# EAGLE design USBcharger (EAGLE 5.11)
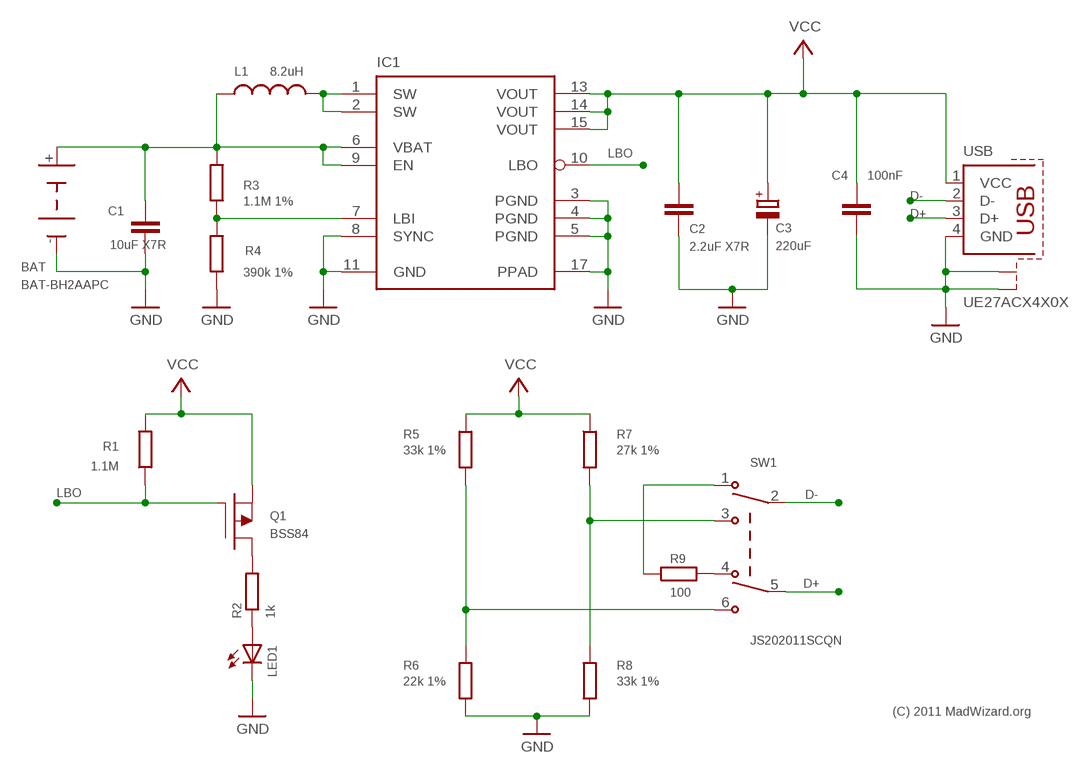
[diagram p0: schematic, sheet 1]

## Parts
BAT  BAT-BH2AAPC  [BH2AAPC]
C1  10uF X7R  C0805  [CAPC2012X130N]
C2  2.2uF X7R  C0805  [CAPC2012X130N]
C3  220uF  CPMLD-B  [CAPMP3528X210N]
C4  100nF  C0603  [CAPC1608X55N]
IC1  TPS61032  [MO-153+PAD]
L1  8.2uH  LWE-HCI-13MM  [7443550820]
LED1  LED0603  [LEDC1608X60N]
Q1  BSS84  PFET_SOT23  [SOT95P240X110-3N]
R1  1.1M  R0603  [RESC1508X63N]
R2  1k  R0603  [RESC1508X63N]
R3  1.1M 1%  R0603  [RESC1508X63N]
R4  390k 1%  R0603  [RESC1508X63N]
R5  33k 1%  R0603  [RESC1508X63N]
R6  22k 1%  R0603  [RESC1508X63N]
R7  27k 1%  R0603  [RESC1508X63N]
R8  33k 1%  R0603  [RESC1508X63N]
R9  100  R0603  [RESC1508X63N]
SW1  JS202011SCQN  [JS202011SCQN]
USB  UE27ACX4X0X  USB-A-RECEPTACLE  [USB-A-RECEPTACLE]

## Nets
D+: SW1.5(2COM) USB.3(D+)
D-: SW1.2(1COM) USB.2(D-)
GND: BAT.- C1.2 C2.2 C3.2(-) C4.2 IC1.3(PGND) IC1.4(PGND) IC1.5(PGND) IC1.8(SYNC) IC1.11(GND) IC1.17(PPAD) LED1.1(C) R4.1 R6.2 R8.2 USB.4(GND) USB.S1 USB.S2
IDEV-: R7.2 R8.1 SW1.3(1B)
LBI: IC1.7(LBI) R3.1 R4.2
LBO: IC1.10(LBO) Q1.1(GATE) R1.1
N$1: Q1.3(DRAIN) R2.2
N$2: R9.1 SW1.1(1A)
N$3: LED1.2(A) R2.1
N$4: R9.2 SW1.4(2A)
RR3: R5.2 R6.1 SW1.6(2B)
SW: IC1.1(SW) IC1.2(SW) L1.2
VBAT: BAT.+ C1.1 IC1.6(VBAT) IC1.9(EN) L1.1 R3.2
VCC: C2.1 C3.1(+) C4.1 IC1.13(VOUT) IC1.14(VOUT) IC1.15(VOUT) Q1.2(SOURCE) R1.2 R5.1 R7.1 USB.1(VCC)

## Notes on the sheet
- (C) 2011 MadWizard.org

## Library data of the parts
BAT = mw-special:BAT-BH2AAPC
C1 C2 C4 = mw-passive:C
C3 = mw-passive:CP
IC1 = mw-ti:TPS61032
L1 = mw-wurth:L
LED1 = mw-diodes:LED
Q1 = mw-transistors:PFET_
R1-R9 = mw-passive:R
SW1 = mw-ck:JS202011SCQN
USB = mw-special:USB-A-RECEPTACLE; OC_FARNELL: unknown; OC_NEWARK: unknown

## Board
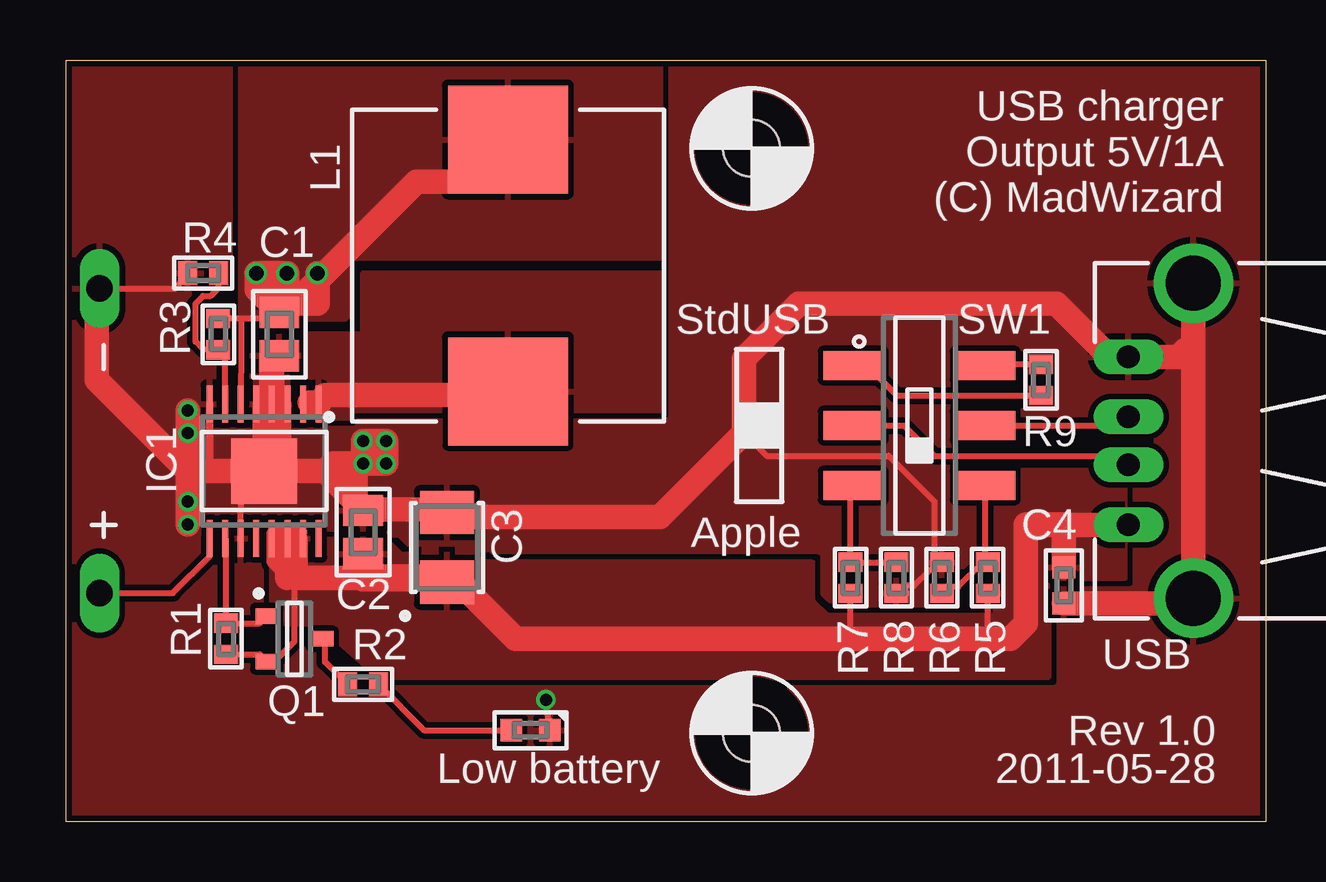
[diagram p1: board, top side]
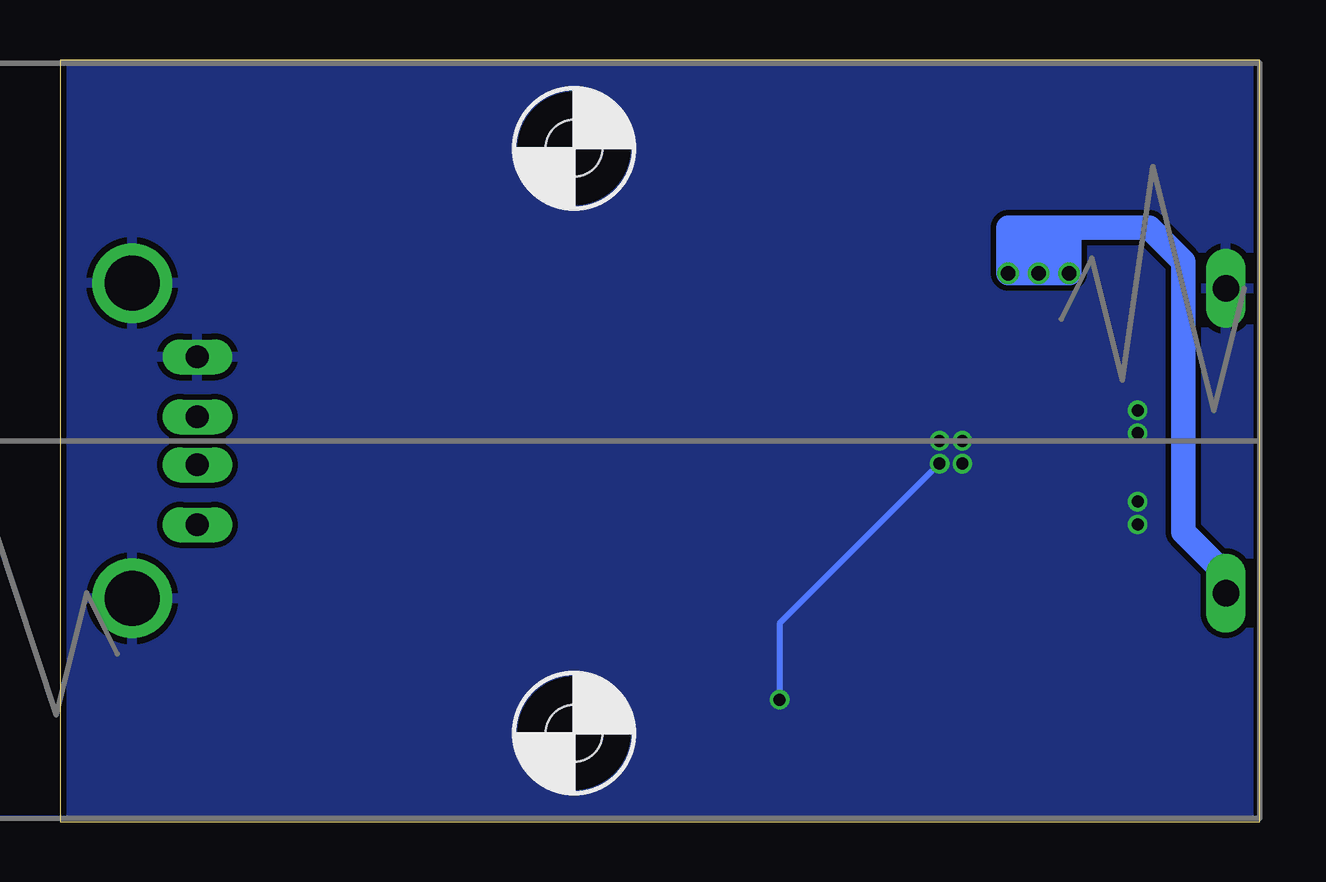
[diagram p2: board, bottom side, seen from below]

Size 50 x 31.75 mm. Coordinates in mm from the lower left corner, seen from the top.
Outline: 0,0 0,31.75 50,31.75 50,0 0,0
Copper layers (1*16): Top 0.035mm / dielectric 1.5mm / Bottom 0.035mm
Design rules "ITead_rule *": minimum track width 8mil, minimum drill 12mil, track to track 9mil, track to pad 9mil, pad to pad 9mil, via to via 9mil, smd to smd 0mil, copper to edge 10mil, drill to drill 10mil, minimum pad ring 10mil, minimum via ring 6mil, stop-mask expansion 2mil, vias tented up to drill 100mil, thermal gap 10mil

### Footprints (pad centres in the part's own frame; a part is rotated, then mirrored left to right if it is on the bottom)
BH2AAPC = drill 1.1 long: + 27.178,-6.35; - 27.178,6.35 | hole 2.362: 0,12.192; 0,-12.192
CAPC2012X130N = smd 1.3 x 1.65: 1 -0.9,0; 2 0.9,0
CAPMP3528X210N = smd 1.8 x 2.25: 1 -1.45,0; 2 1.45,0
CAPC1608X55N = smd 0.9 x 0.95: 1 -0.75,0; 2 0.75,0
MO-153+PAD = smd 0.25 x 1.55: 1 -2.275,-2.8; 2 -1.625,-2.8; 3 -0.975,-2.8; 4 -0.325,-2.8; 5 0.325,-2.8; 6 0.975,-2.8; 7 1.625,-2.8; 8 2.275,-2.8; 9 2.275,2.8; 10 1.625,2.8; 11 0.975,2.8; 12 0.325,2.8; 13 -0.325,2.8; 14 -0.975,2.8; 15 -1.625,2.8; 16 -2.275,2.8 | smd 2.74 x 2.74: 17 0,0
7443550820 = smd 4.5 x 5: 1 -5.25,0; 2 5.25,0
LEDC1608X60N = smd 0.9 x 0.95: 1 -0.8,0; 2 0.8,0
SOT95P240X110-3N = smd 0.95 x 0.65: 1 -1.15,0.95; 2 -1.15,-0.95; 3 1.15,0
RESC1508X63N = smd 0.8 x 1: 1 -0.65,0; 2 0.65,0
JS202011SCQN = smd 1.2 x 2.5: 1 -2.5,-2.75; 2 0,-2.75; 3 2.5,-2.75; 4 -2.5,2.75; 5 0,2.75; 6 2.5,2.75
USB-A-RECEPTACLE = drill 0.95 long: 1 -3.5,2.71; 2 -1,2.71; 3 1,2.71; 4 3.5,2.71 | drill 2.3 pad 2.9 round: S1 -6.57,0; S2 6.57,0

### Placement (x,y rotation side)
BAT  28.57,15.88 0 bottom
C1  8.89,20.32 270 top
C2  12.38,12.06 90 top
C3  15.88,11.43 90 top
C4  41.59,9.84 270 top
IC1  8.26,14.61 180 top
L1  18.41,23.18 270 top
LED1  19.37,3.81 180 top
Q1  9.53,7.62 0 top
R1  6.67,7.62 270 top
R2  12.38,5.71 180 top
R3  6.35,20.32 90 top
R4  5.71,22.86 0 top
R5  38.42,10.16 90 top
R6  36.51,10.16 90 top
R7  32.7,10.16 90 top
R8  34.61,10.16 270 top
R9  40.64,18.41 90 top
SW1  35.56,16.51 270 top
USB  46.99,15.88 90 top

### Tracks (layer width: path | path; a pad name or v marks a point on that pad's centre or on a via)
D+
  Top 0.203: 44.65,16.51 45.09,16.51
  Top 0.254: SW1.5 44.65,16.51 USB.3
D-
  Top 0.203: 43.18,15.24 43.55,14.88
  Top 0.254: SW1.2 34.92,16.51 36.2,15.24 43.18,15.24 | 43.55,14.88 USB.2
GND  (via drill 0.5)
  Top 0.203: 8.58,19.32 C1.2 | 36.2,11.11 36.5,10.81 R6.2
  Top 0.254: 7.93,15.56 IC1.17 7.3,14.29 IC1.11 | 1.27,22.23 BAT.- 4.57,22.23 R4.1 | 46.99,19.37 USB.S2 | 44.45,19.37 USB.4 | 36.2,11.11 36.2,13.34 34.29,15.24 29.21,15.24 28.26,16.19 | v20,5.08 20,4.76 LED1.1 | R8.2 34.94,9.84 35.34,9.84 35.98,10.48 36.73,10.72 R6.2 | 12.06,13.02 12.12,12.96 C2.2
  Top 0.305: IC1.3 9.23,14.63 IC1.17 8.58,14.93 | IC1.5 7.93,16.18 7.94,14.61 | IC1.8 5.98,14.87 5.08,14.61 | 28.26,16.19
  Top 1.016: 1.27,22.23 1.27,18.41 4.76,14.92 | 5.08,14.61 4.76,14.92 | 5.08,14.61 7.94,14.61 IC1.17 10.79,14.61 | 10.79,14.61 C2.2 12.65,12.96 12.7,13.02 15.88,13.02 C3.2 15.88,12.7 24.77,12.7 28.26,16.19 28.26,19.3 30.55,21.59 41.27,21.59 43.5,19.37 44.45,19.37 | 8.58,14.93 IC1.4 | v5.08,17.14 v5.08,16.19 5.08,15.24 4.76,14.92 | v5.08,12.38 v5.08,13.34 5.08,14.61 | 10.79,14.61 11.11,14.92 v12.38,14.92 | v12.38,14.92 v13.34,14.92 v13.34,15.88 v12.38,15.88 v12.38,14.92 | 12.06,13.02 12.06,14.61 | 46.99,19.37 USB.S1 46.78,9.09 C4.2 | 46.99,19.37 46.99,22.54 | USB.4 46.36,19.38 46.67,19.68 46.99,19.37
  Top 1.067: IC1.4 8.58,19.32
  Bottom 0.254: v13.34,14.92 20,8.26 v20,5.08
  pour Top (rank 5): -0.64,32.7 -0.64,-0.64 50.16,-0.64 50.16,32.7
  pour Bottom (rank 5): -0.95,33.66 -0.95,-0.95 51.12,-0.95 51.12,32.7 50.8,32.7 50.8,33.66
IDEV-
  Top 0.203: 32.7,14.29 32.85,13.97 SW1.3
  Top 0.254: 32.7,14.29 R7.2 R8.1
LBI
  Top 0.254: IC1.7 6.63,19.39 R3.1 6.33,19.68 5.71,19.68 5.4,20 5.4,21.59 5.71,21.91 6.03,21.91 6.37,22.24 R4.2
LBO
  Top 0.254: IC1.10 6.67,11.77 R1.1 8.07,8.27 Q1.1
N$1
  Top 0.254: R2.2 10.79,6.65 10.79,7.62 Q1.3
N$2
  Top 0.203: 32.07,18.73 32.05,19.04
  Top 0.254: R9.1 34.62,17.77 33.66,18.73 32.7,18.73 32.38,19.05 32.05,19.04 | 32.07,18.73 33.02,19.22 SW1.1
N$3
  Top 0.254: 13.15,5.58 13.02,5.71 R2.1 14.92,3.81 LED1.2
N$4
  Top 0.203: 37.78,19.05 39.05,18.9 SW1.4
  Top 0.254: 37.78,19.05 39.05,19.05 38.43,19.07 R9.2
RR3
  Top 0.203: R5.2 38.31,11.23
  Top 0.254: 38.31,11.23 SW1.6 | R6.1 36.8,9.8 37.2,9.8 38.21,10.81 R5.2
SW
  Top 0.406: 17.57,17.72 L1.2 | 10.16,17.46 10.1,17.41 IC1.2 | 10.48,17.46 IC1.1
  Top 1.016: IC1.1 10.79,17.78 17.57,17.78 17.57,17.72 | 10.16,17.46 10.48,17.46
  pour Top: 24.77,22.86 24.77,17.14 11.75,17.14 11.75,16.83 10.16,16.83 10.16,20.32 12.38,20.32 12.38,22.86
VBAT  (via drill 0.6)
  Top 0.254: BAT.+ 4.45,9.53 5.98,11.06 IC1.9 | C1.1 9.15,21.27 | C1.1 8.52,21.22 | IC1.6 7.3,19.97 7.3,20.97 | 7.3,20.97 8.64,20.97 C1.1 | 7.3,20.97 R3.2
  Top 1.016: L1.1 17.14,27.62 16.19,26.67 14.61,26.67 10.79,22.86 9.15,21.27 | C1.1 7.94,22.17 v7.94,22.86 v9.21,22.86 | v9.21,22.86 9.21,21.59 10.48,21.59 v10.48,22.86 | v9.21,22.86 8.57,22.86 8.57,22.54
  Bottom 1.016: BAT.+ 1.27,10.16 3.17,12.06 3.17,23.34 4.59,24.77 7.94,24.77 | 7.94,24.77 v7.94,22.86 v9.21,22.86 | v9.21,22.86 9.21,24.32 | v10.48,22.86 10.48,24.77 7.94,24.77 | v10.48,22.86 v9.21,22.86 | v10.48,22.86 10.16,23.18 10.16,24.13 9.84,23.81 8.26,23.81
  pour Top: 7.3,32.07 24.77,32.07 24.77,23.5 11.75,23.5 11.75,21.08 11.62,20.95 7.3,20.95 7.3,24.45
VCC
  Top 0.254: R7.1 32.7,7.94 33.02,7.62 | R5.1 38.42,7.94 38.73,7.62 | R1.2 8.07,6.97 Q1.2 8.69,6.67 9.53,7.5 9.53,10.16
  Top 0.406: 9.21,11.78 IC1.14 | 9.21,10.16 8.58,10.79 IC1.13 8.57,11.81 8.57,12.06 9.84,12.06 | IC1.15 9.88,10.52 9.37,10.32
  Top 1.016: C2.1 12.38,10.16 9.53,10.16 9.37,10.32 9.21,10.16 9.21,11.78 | 15.7,10.16 C3.1 16.19,10.16 18.73,7.62 33.02,7.62 38.73,7.62 39.37,7.62 40.01,8.26 40.01,12.38 41.59,12.38 40.93,12.38 41.59,12.38 | 41.59,12.38 USB.1 | 41.59,12.38 C4.1
  Top 1.15: 12.38,10.16 15.7,10.16
  pour Top: 8.57,12.06 8.57,8.26 10.48,8.26 13.02,6.03 40.96,6.03 40.96,10.16 44.13,10.16 44.13,14.61 38.73,14.61 38.73,8.57 31.75,8.57 31.11,9.21 31.11,10.79 17.46,10.79 17.14,11.11 13.97,11.11 13.34,11.75 10.48,11.75 10.16,12.06

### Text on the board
tNames: USB charger | Output 5V/1A | (C) MadWizard | StdUSB | Apple | Rev 1.0 | Low battery | 2011-05-28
